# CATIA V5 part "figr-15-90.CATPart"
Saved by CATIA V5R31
Part number: Part1
Bounding box of the stored display mesh (mm): x -45.183 to 59.676, y -22.214 to 29.903, z -4 to 1
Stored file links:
  D:\PROJECTS\Project 2021\US EDITION\CATIA V5 6R 2021\Resources\Part Files\c15_catia_v5_6r2021_prt\figr-15-90.CATPart
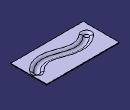
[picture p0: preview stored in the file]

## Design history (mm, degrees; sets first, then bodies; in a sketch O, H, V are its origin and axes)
SheetMetalParameters1: Thickness 1, BendRadius 5, KFactor 0.5 {= log(min(100,max(20*SheetMetalParameters1.BendRadius,SheetMetalParameters1.Thickness)/SheetMetalParameters1.Thickness))/log(100)/2}, ReliefRadialLength 1, ReliefAxialLength 2, MinimumBendRadius 0
Body1 (main body)
  Sketch1 on xy-plane, origin (0, 0, 0), H (1, 0, 0), V (0, 1, 0)
    line L1 (-45.1833, 29.903) -> (59.6761, 29.903)
    line L2 (59.6761, 29.903) -> (59.6761, -22.2137)
    line L3 (59.6761, -22.2137) -> (-45.1833, -22.2137)
    line L4 (-45.1833, -22.2137) -> (-45.1833, 29.903)
    horizontal: L1 H, L3 H
    vertical: L2 V, L4 V
  Wall1: Thickness 1, Profile Sketch1
  Sketch2 on face of Wall1, origin (0, 0, 1), H (1, 0, 0), V (0, 1, 0)
    spline S1 through (-31.3214, -3.7025) (-6.2947, 5.2247) (29.3365, -3.7025) (50.9697, 6.9251)
  d_Stamp1: Stamp_FilletRadius 4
